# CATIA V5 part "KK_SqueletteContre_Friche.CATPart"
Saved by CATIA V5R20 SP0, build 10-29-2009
Part number: Squelette_contre_fiche_superieure
Publications: "Plan reference contre fiche superieue"
Bounding box of the stored display mesh (mm): x -2022.095 to -861.81, y 649.315 to 1252.338, z -967.22 to 0
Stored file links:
  G:\Khaled_CFAO_2011\ST2M\ST2M_GR2\aboulegue\Khaled\CAD_thinkMOTION\KK_SqueletteContre_Friche.CATPart
  G:\Khaled_CFAO_2011\ST2M\ST2M_GR2\aboulegue\Khaled\CAD_thinkMOTION\KK_Train_Atterrissage.CATProduct
  G:\Khaled_CFAO_2011\ST2M\ST2M_GR2\aboulegue\CFAO_aboulegue\CFAO_aboulegue_fichiers_catia\Squelette_general.CATPart
  G:\Khaled_CFAO_2011\ST2M\ST2M_GR2\aboulegue\CFAO_aboulegue\CFAO_aboulegue_fichiers_catia\Squelette_contre_fiche_inferieure.CATPart
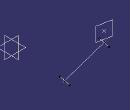
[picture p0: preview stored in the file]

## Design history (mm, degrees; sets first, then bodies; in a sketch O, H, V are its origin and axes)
Set1
  Point1 "Point.12": linked copy from another document
  Point2 "Point.15": linked copy from another document
  Point3 "Point.16": linked copy from another document
Set2 "Set squelette contre fiche superieure"
  Line1: type PtPt, FirstPoint Point1, SecondPoint Point2
  Plane1 "Plan reference contre fiche superieue": type 1Line1Pt, RefPoint Point3, Line Line1
  Line2: type Normal, RefPoint Point1, RefSkin Plane1, Start -200, End 200
  Line3: type Normal, RefPoint Point2, RefSkin Plane1, Start -200, End 200
Body1 (main body)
